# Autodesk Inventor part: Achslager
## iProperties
Created: 2003-03
Part Number: Achslager
Material: Aluminium
Document SubType Name: Modellieren
Designer: Administrator
Control State: 0
Master: False
Checked Out: False
Shininess: 20.0
Angle Display Precision: 2
Document Length Units: 11269
Document Angle Units: 11279
Document Time Units: 11290
Document Mass Units: 11283
Document Length Units Precision: 3
Document Angle Units Precision: 2
Density: 0.0
Volumn: 0.0
Area: 0.0
PropertySet Name: Model Information
Author: Administrator
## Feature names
1. Extrusion1
2. Bohrung1 [Hole]
3. Fase2 [Chamfer]
